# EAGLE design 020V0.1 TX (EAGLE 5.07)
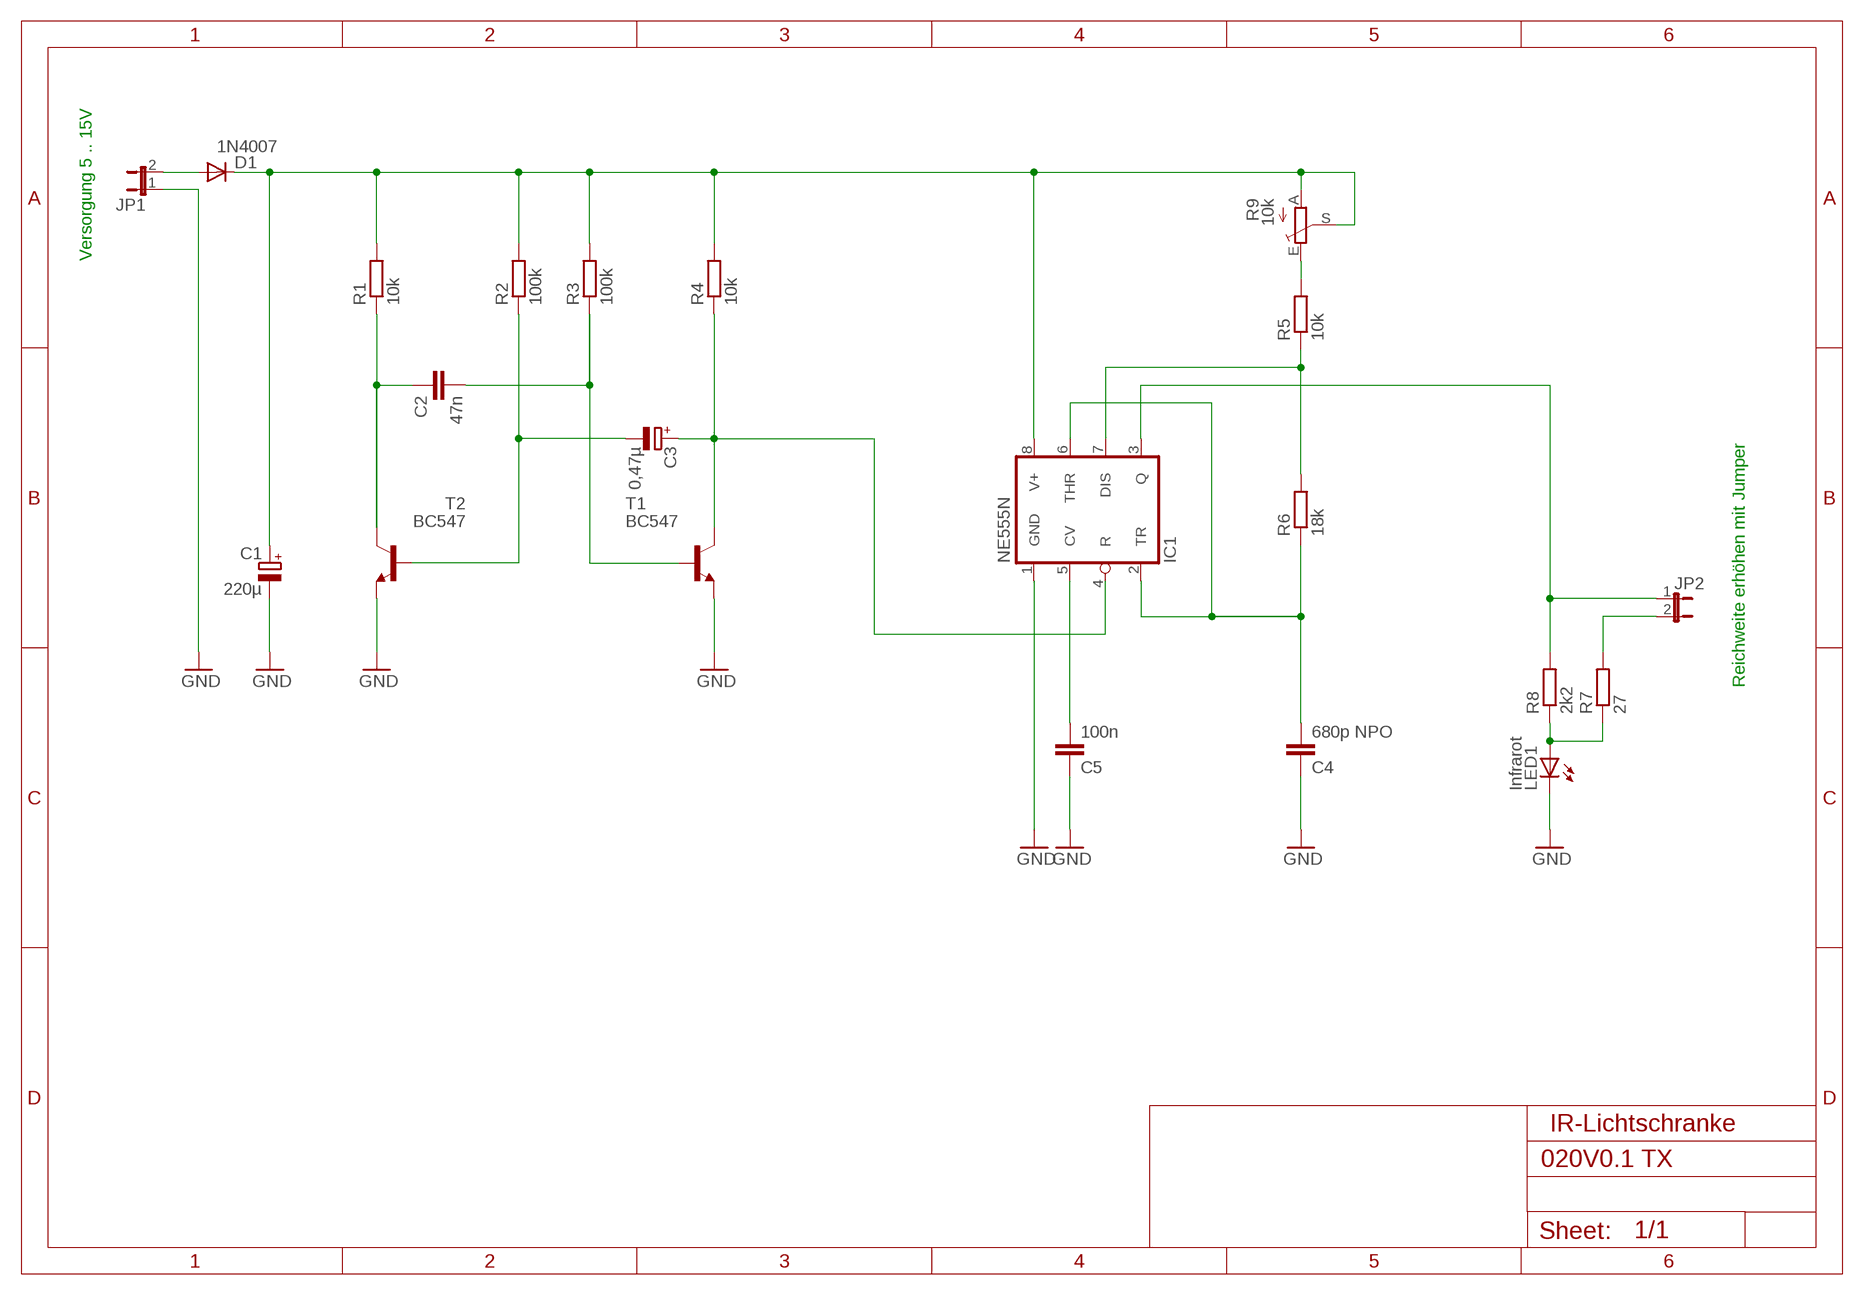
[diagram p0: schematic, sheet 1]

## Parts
C1  220µ  CPOL-EUE2.5-6  [E2,5-6]
C2  47n  C-EU050-025X075  [C050-025X075]
C3  0,47µ  CPOL-EUE5-4  [E5-4]
C4  680p NPO  C-EU050-025X075  [C050-025X075]
C5  100n  C-EU050-025X075  [C050-025X075]
D1  1N4007  1N4004  [DO41-10]
IC1  NE555N  [DIL08]
JP1  JP1E  [JP1]
JP2  JP1E  [JP1]
LED1  Infrarot  LED5MM  [LED5MM]
R1  10k  R-EU_0207/10  [0207/10]
R2  100k  R-EU_0207/10  [0207/10]
R3  100k  R-EU_0207/10  [0207/10]
R4  10k  R-EU_0207/10  [0207/10]
R5  10k  R-EU_0207/10  [0207/10]
R6  18k  R-EU_0207/10  [0207/10]
R7  27  R-EU_0207/10  [0207/10]
R8  2k2  R-EU_0207/10  [0207/10]
R9  10k  TRIM_EU-S63X  [S63X]
T1  BC547  [TO92-5]
T2  BC547  [TO92-5]

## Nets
GND: C1.- C4.1 C5.1 IC1.1(GND) JP1.1 LED1.K(C) T1.1(E) T2.1(E)
N$1: C1.+ D1.C IC1.8(V+) R1.2 R2.2 R3.2 R4.2 R9.A R9.S
N$2: R5.2 R9.E
N$3: C2.1 R1.1 T2.3(C)
N$4: C2.2 R3.1 T1.2(B)
N$5: C3.- R2.1 T2.2(B)
N$6: C3.+ IC1.4(R) R4.1 T1.3(C)
N$7: C5.2 IC1.5(CV)
N$8: C4.2 IC1.2(TR) IC1.6(THR) R6.1
N$9: IC1.7(DIS) R5.1 R6.2
N$10: IC1.3(Q) JP2.1 R8.2
N$11: LED1.A R7.1 R8.1
N$12: JP2.2 R7.2
N$17: D1.A JP1.2

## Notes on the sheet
- Versorgung 5 .. 15V
- Reichweite erhöhen mit Jumper
- IR-Lichtschranke

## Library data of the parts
C1 C3 = rcl:CPOL-EU: POLARIZED CAPACITOR, European symbol
C2 C4 C5 = rcl:C-EU: CAPACITOR, European symbol
D1 = diode:1N4004: DIODE
IC1 = linear:*555: TIMER
JP1 JP2 = jumper:JP1E: JUMPER
LED1 = led:LED: LED
R1-R8 = rcl:R-EU_: RESISTOR, European symbol
R9 = pot:TRIM_EU-: POTENTIOMETER
T1 T2 = armin:BC547: NPN TRANSISTOR

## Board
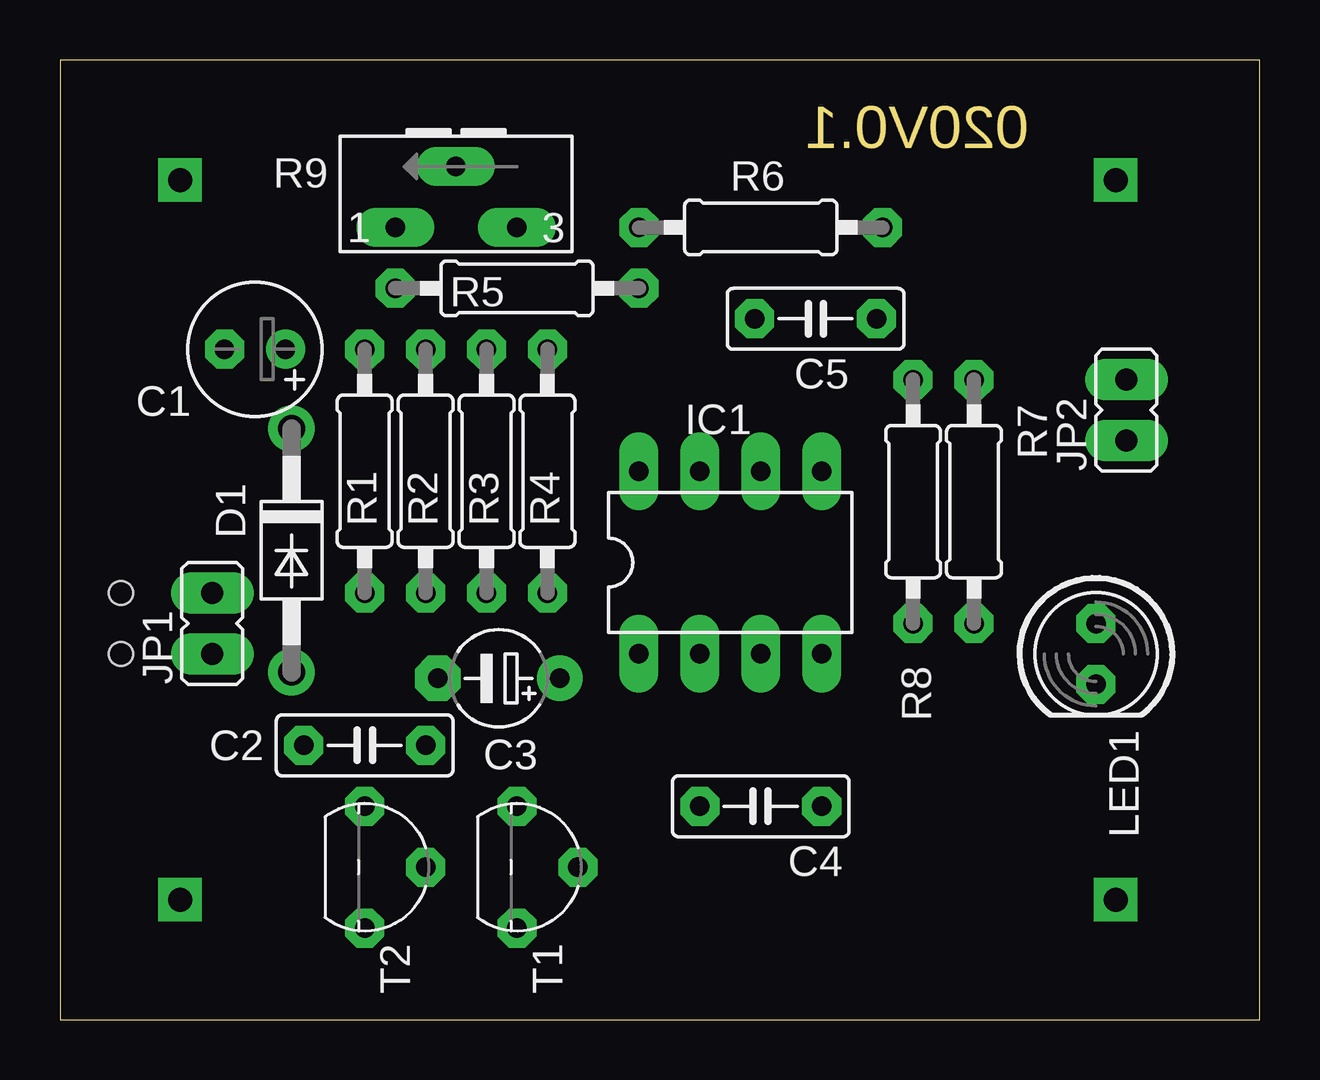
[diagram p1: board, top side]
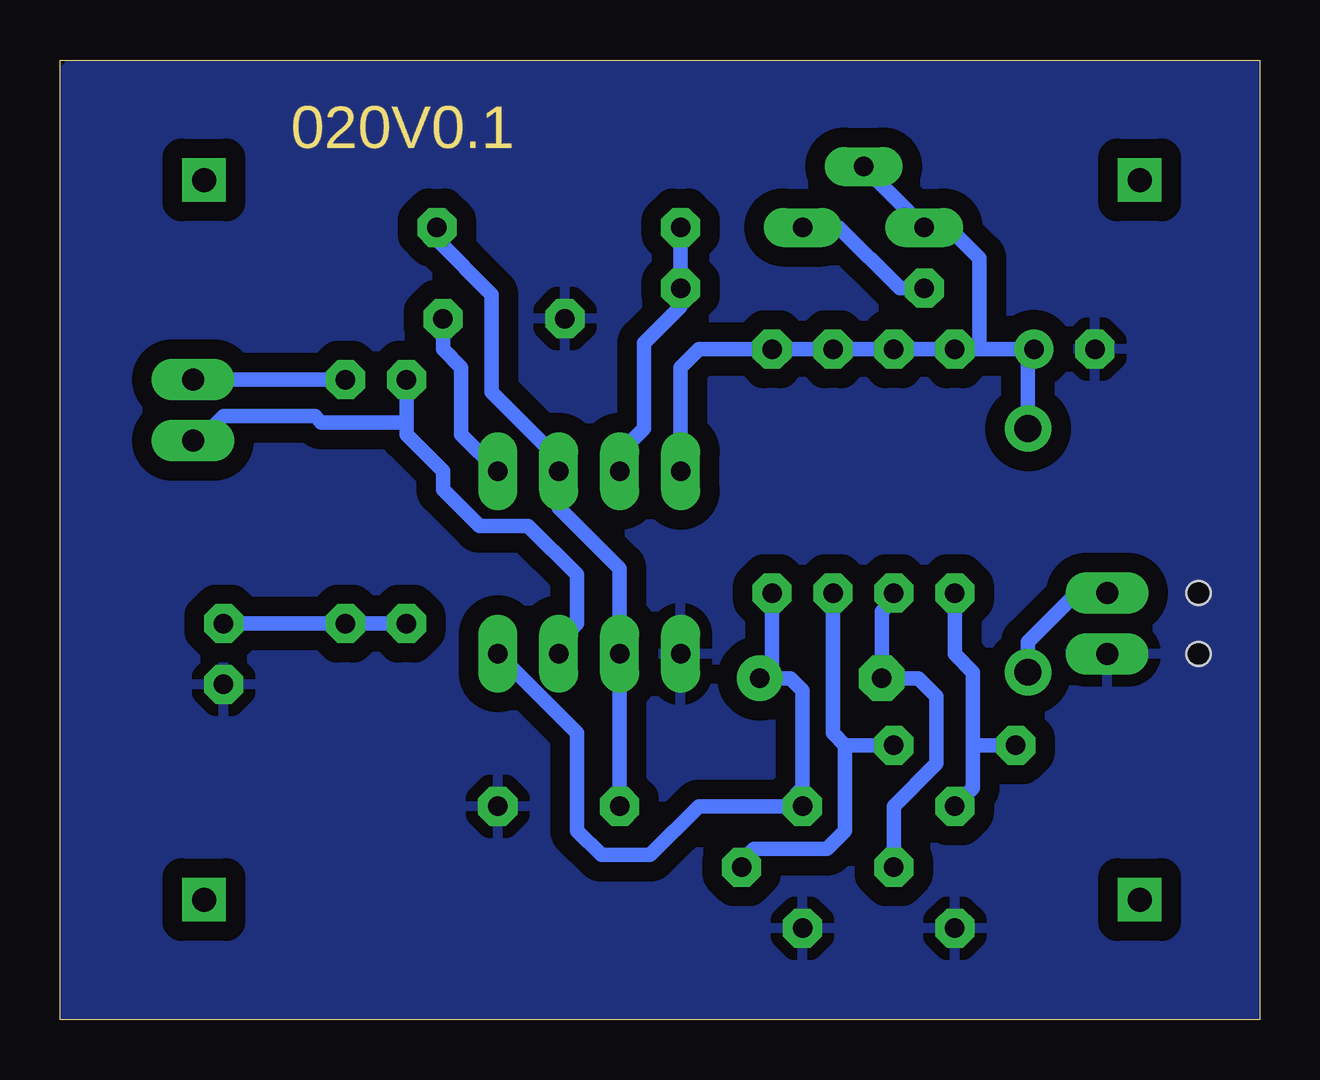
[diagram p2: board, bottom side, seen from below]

Size 50 x 40 mm. Coordinates in mm from the lower left corner, seen from the top.
Outline: 0,0 50,0 50,40 0,40 0,0
Copper layers (1*16): Top 0.035mm / dielectric 1.5mm / Bottom 0.035mm
Design rules "default *": minimum track width 10mil, minimum drill 24mil, track to track 32mil, track to pad 32mil, pad to pad 20mil, via to via 20mil, smd to smd 8mil, copper to edge 1mil, drill to drill 8mil, minimum pad ring 16mil, minimum via ring 16mil, stop-mask expansion 4mil, vias tented up to drill 0mil, thermal gap 20mil
Holes 1 mm at 2.54,15.24 2.54,17.78

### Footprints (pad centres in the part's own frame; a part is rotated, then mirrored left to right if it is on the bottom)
E2,5-6 = drill 0.813 pad 1.6 round: + -1.27,0 | drill 0.813 pad 1.6 octagon: - 1.27,0
C050-025X075 = drill 0.813 octagon: 1 -2.54,0; 2 2.54,0
E5-4 = drill 0.813 pad 1.905 round: + -2.54,0 | drill 0.813 pad 1.905 octagon: - 2.54,0
DO41-10 = drill 1.118 round: A 5.08,0; C -5.08,0
DIL08 = drill 0.813 long: 1 -3.81,-3.81; 2 -1.27,-3.81; 3 1.27,-3.81; 4 3.81,-3.81; 5 3.81,3.81; 6 1.27,3.81; 7 -1.27,3.81; 8 -3.81,3.81
JP1 = drill 0.914 long: 1 0,-1.27; 2 0,1.27
LED5MM = drill 0.813 octagon: A -1.27,0; K 1.27,0
0207/10 = drill 0.813 octagon: 1 -5.08,0; 2 5.08,0
S63X = drill 0.813 long: A 2.54,0; E -2.54,0; S 0,-2.54
TO92-5 = drill 0.813 octagon: 1 2.54,0; 2 0,2.54; 3 -2.54,0

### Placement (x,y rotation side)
C1  8.13,27.94 180 top
C2  12.7,11.43 0 top
C3  18.29,14.22 180 top
C4  29.21,8.89 180 top
C5  31.5,29.21 0 top
D1  9.65,19.56 270 top
IC1  27.94,19.05 0 top
JP1  6.35,16.51 0 top
JP2  44.45,25.4 0 top
LED1  43.18,15.24 270 top
R1  12.7,22.86 90 top
R2  15.24,22.86 90 top
R3  17.78,22.86 90 top
R4  20.32,22.86 90 top
R5  19.05,30.48 180 top
R6  29.21,33.02 180 top
R7  38.1,21.59 90 top
R8  35.56,21.59 90 top
R9  16.51,33.02 180 top
T1  19.05,6.35 270 top
T2  12.7,6.35 270 top

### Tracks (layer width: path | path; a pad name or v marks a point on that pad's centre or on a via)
GND
  pour Bottom: 0,40.13 0,0 49.78,0 49.78,39.62 49.53,39.88 1.52,39.88
  pour Bottom: 29.21,38.61 29.21,35.31 41.91,35.31 41.91,35.81 41.91,39.12 29.21,39.12
N$1
  Bottom 0.61: R1.2 R2.2 R3.2 R4.2 23.37,27.94 24.13,27.18 IC1.8 | R1.2 12.45,27.69 | R9.S R9.A 12.95,33.02 11.68,31.75 11.68,27.94 | 11.68,27.94 R1.2 | 11.68,27.94 C1.+ 9.65,27.69 D1.C
N$2
  Bottom 0.61: R5.2 14.99,30.48 17.53,33.02 R9.E
N$3
  Bottom 0.61: R1.1 12.7,15.24 11.94,14.48 11.94,11.43 | 11.94,11.43 11.94,9.65 T2.3 | 11.94,11.43 C2.1
N$4
  Bottom 0.61: R3.1 17.78,11.94 17.27,11.43 | 17.27,11.43 C2.2 | 17.27,11.43 17.27,7.87 18.03,7.11 21.08,7.11 21.59,6.6 T1.2
N$5
  Bottom 0.61: R2.1 15.24,17.53 15.75,17.02 C3.- 14.22,14.22 13.46,13.46 13.46,10.67 15.24,8.89 T2.2
N$6
  Bottom 0.61: T1.3 19.3,8.89 | IC1.4 28.45,11.94 28.45,7.87 27.43,6.86 25.4,6.86 23.37,8.89 19.3,8.89 | 19.3,8.89 19.05,9.14 | R4.1 20.32,14.73 C3.+ 19.56,14.22 19.05,13.72 19.05,9.65 19.3,9.4 19.3,8.89
N$7
  Bottom 0.61: C5.2 34.04,27.94 33.27,27.18 33.27,24.38 IC1.5
N$8
  Bottom 0.61: C4.2 IC1.2 26.67,18.8 29.21,21.34 IC1.6 29.21,23.37 32,26.16 32,30.23 34.29,32.51 R6.1
N$9
  Bottom 0.61: R6.2 R5.1 24.13,29.72 25.65,28.19 25.65,24.64 26.67,23.62 IC1.7
N$10
  Bottom 0.61: IC1.3 29.21,15.75 28.45,16.51 28.45,18.54 30.48,20.57 32.51,20.57 34.04,22.1 34.04,22.86 35.56,24.38 35.56,24.89 | 35.56,24.89 R8.2 | JP2.1 44.2,24.13 43.18,25.15 39.37,25.15 39.12,24.89 35.56,24.89
N$11
  Bottom 0.61: R8.1 R7.1 LED1.A
N$12
  Bottom 0.61: R7.2 JP2.2
N$13  (via drill 1)
  other vias: 5,5
N$14  (via drill 1)
  other vias: 44,5
N$15  (via drill 1)
  other vias: 5,35
N$16  (via drill 1)
  other vias: 44,35
N$17
  Bottom 0.61: JP1.2 7.62,17.78 9.65,15.75 D1.A

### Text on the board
Dimension: 020V0.1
